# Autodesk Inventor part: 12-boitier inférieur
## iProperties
Created: 2011-02
Part Number: 12-boitier inférieur
Document SubType Name: Modeling
Designer: eric
Density: 1 g/cm^3
Author: eric
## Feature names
1. Base1
